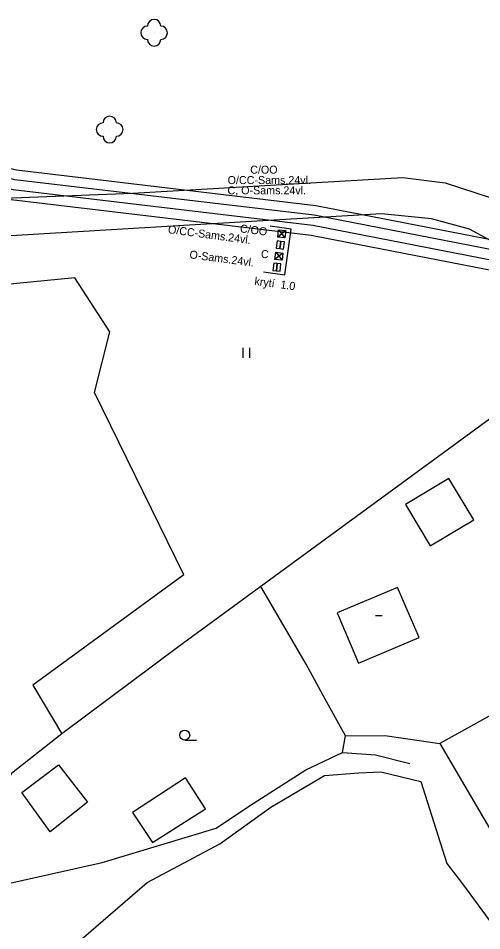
# Model space of a CAD drawing. Extents: x -836739 to -834468, y -1071001 to -1070126.
# Drawn here: x -836526 to -836491.3, y -1070268.6 to -1070200.2 of the extents above; entities that cross this region are included whole.
import ezdxf

# ---------------------------------------------------------------- set-up
doc = ezdxf.new("R2010")
doc.units = 0
for name, color, linetype in [('f001_pol_linie', 7, 'Continuous'), ('f001_pol_znacky', 7, 'Continuous'), ('f003_opt_sit_texty', 7, 'Continuous'), ('f006_osa_trasy', 7, 'Continuous'), ('f007_rezkynet_texty', 7, 'Continuous'), ('f007_rezkynet_znacky', 7, 'Continuous'), ('f309_trubka', 7, 'Continuous')]:
    doc.layers.add(name, color=color, linetype=linetype)

msp = doc.modelspace()

# ---------------------------------------------------------------- linework, layer by layer
at = {"layer": 'f001_pol_linie'}
for points in [[(-836565.55, -1070255.75), (-836568.29, -1070246.94), (-836565.3, -1070243.45), (-836558.59, -1070239.29), (-836553.32, -1070234.26), (-836550.36, -1070230.73), (-836544.63, -1070222.38), (-836541.42, -1070218.21), (-836539.02, -1070215.95), (-836535.5, -1070213.99), (-836517.48, -1070213.29), (-836497.22, -1070212.11), (-836494.05, -1070212.5), (-836489.39, -1070214.02), (-836485.93, -1070216.36), (-836482.28, -1070220.4), (-836478.23, -1070227.56), (-836471.79, -1070243.33), (-836465.92, -1070256.62), (-836463.85, -1070260.25), (-836463.13, -1070260.78)], [(-836466.54, -1070263.19), (-836474.56, -1070243.73), (-836478.12, -1070235.21), (-836483.33, -1070224.14), (-836486.58, -1070219.75), (-836489.27, -1070217.57), (-836492.22, -1070215.97), (-836495.08, -1070215.2), (-836498.82, -1070214.84), (-836513.64, -1070215.7), (-836532.05, -1070216.8), (-836534.5, -1070217.36), (-836537.57, -1070219.18), (-836540.24, -1070221.43), (-836545, -1070227.8), (-836549.52, -1070233.43), (-836552.32, -1070236.92), (-836557.98, -1070243.27), (-836562.8, -1070249.08), (-836563.01, -1070249.54), (-836561.48, -1070254.69), (-836565.55, -1070255.75)], [(-836513.64, -1070241.9), (-836520.33, -1070228.24), (-836519.17, -1070223.67), (-836521.79, -1070219.62), (-836540.24, -1070221.43)], [(-836481.49, -1070241.59), (-836481.74, -1070241), (-836484.22, -1070225.45), (-836507.86, -1070242.77), (-836514.01, -1070247.28)], [(-836493.77, -1070234.68), (-836497.03, -1070236.63), (-836495.17, -1070239.73), (-836491.91, -1070237.78), (-836493.77, -1070234.68)], [(-836513.64, -1070241.9), (-836524.94, -1070250.18), (-836522.78, -1070253.83)], [(-836501.52, -1070253.97), (-836503.04, -1070251.23), (-836504.47, -1070248.59), (-836507.86, -1070242.77)], [(-836497.61, -1070242.84), (-836502.15, -1070244.76)], [(-836496.01, -1070246.6), (-836497.61, -1070242.84)], [(-836502.15, -1070244.76), (-836500.55, -1070248.53)], [(-836500.55, -1070248.53), (-836496.01, -1070246.6)], [(-836514.01, -1070247.28), (-836522.78, -1070253.83)], [(-836484.13, -1070248.82), (-836494.44, -1070254.55), (-836490.71, -1070260.96)], [(-836522.78, -1070253.83), (-836526.55, -1070256.8), (-836527.02, -1070257.7), (-836529.71, -1070265.69)], [(-836508.71, -1070259.23), (-836504.49, -1070256.53), (-836501.74, -1070255.22), (-836501.52, -1070253.97), (-836498.58, -1070253.94), (-836494.44, -1070254.55)], [(-836501.74, -1070255.22), (-836499.27, -1070255.4), (-836496.7, -1070256.04)], [(-836525.78, -1070258.23), (-836523.02, -1070256.16), (-836520.84, -1070258.96)], [(-836521.88, -1070269.71), (-836516.37, -1070264.96), (-836510.93, -1070262.08), (-836507.11, -1070259.33), (-836503.08, -1070256.96), (-836500.52, -1070256.76), (-836498.86, -1070256.68), (-836495.87, -1070257.41), (-836493.93, -1070263.56), (-836492.75, -1070265.06), (-836486.76, -1070273.24)], [(-836517.49, -1070259.73), (-836515.98, -1070261.98), (-836512.01, -1070259.44), (-836513.5, -1070257.12), (-836517.49, -1070259.73)], [(-836523.65, -1070261.18), (-836525.78, -1070258.23)], [(-836529.71, -1070265.69), (-836519.75, -1070263.47), (-836511.22, -1070260.9), (-836508.71, -1070259.23)], [(-836520.84, -1070258.96), (-836523.65, -1070261.18)]]:
    msp.add_lwpolyline(points, dxfattribs=at)
at = {"layer": 'f001_pol_znacky'}
for p, q in [((-836509.18, -1070225.635), (-836509.18, -1070224.885)), ((-836508.68, -1070225.635), (-836508.68, -1070224.885)), ((-836499.27, -1070244.94), (-836498.77, -1070244.94)), ((-836513.57, -1070254.295), (-836512.695, -1070254.295))]:
    msp.add_line(p, q, dxfattribs=at)
for centre, radius in [((-836515.86, -1070201.25), 0.0005), ((-836519.19, -1070208.51), 0.0005), ((-836513.57, -1070253.92), 0.375)]:
    msp.add_circle(centre, radius, dxfattribs=at)
for centre, start, end in [((-836515.86, -1070200.75), 0, 179.99999), ((-836516.36, -1070201.25), 89.99999, 269.99999), ((-836515.36, -1070201.25), 270, 89.99999), ((-836515.86, -1070201.75), 179.99999, 359.99999), ((-836519.19, -1070208.01), 0, 179.99999), ((-836519.69, -1070208.51), 89.99999, 269.99999), ((-836518.69, -1070208.51), 270, 89.99999), ((-836519.19, -1070209.01), 179.99999, 359.99999)]:
    msp.add_arc(centre, 0.5, start, end, dxfattribs=at)
at = {"layer": 'f006_osa_trasy'}
msp.add_lwpolyline([(-836471.29, -1070247.06), (-836475.13, -1070240.07), (-836481.69, -1070223.19), (-836484.06, -1070219.25), (-836486.31, -1070218.35), (-836503.86, -1070214.94), (-836526.3, -1070212.27), (-836553.58, -1070205.67), (-836563.09, -1070200.8), (-836595.87, -1070176.09), (-836614.86, -1070165.34), (-836629.43, -1070164.09), (-836642.16, -1070162.86), (-836653.58, -1070160.22), (-836662.77, -1070161.03), (-836672.46, -1070165.03), (-836697.35, -1070176), (-836703.68, -1070184.13), (-836710.27, -1070188.76)], dxfattribs=at)
at = {"layer": 'f007_rezkynet_znacky'}
for p, q in [((-836505.586, -1070215.985), (-836507.17, -1070215.76)), ((-836505.999, -1070216.089), (-836506.601, -1070216.571)), ((-836506.541, -1070216.029), (-836506.059, -1070216.631)), ((-836506.071, -1070219.401), (-836505.586, -1070215.985)), ((-836506.209, -1070217.769), (-836506.811, -1070218.251)), ((-836506.751, -1070217.709), (-836506.269, -1070218.311)), ((-836507.656, -1070219.176), (-836506.071, -1070219.401))]:
    msp.add_line(p, q, dxfattribs=at)
for points in [[(-836505.999, -1070216.089), (-836506.059, -1070216.631), (-836506.601, -1070216.571), (-836506.541, -1070216.029)], [(-836506.369, -1070216.899), (-836506.64, -1070216.868), (-836506.702, -1070217.409), (-836506.431, -1070217.44)], [(-836506.098, -1070216.93), (-836506.369, -1070216.899), (-836506.431, -1070217.44), (-836506.16, -1070217.471)], [(-836506.209, -1070217.769), (-836506.269, -1070218.311), (-836506.811, -1070218.251), (-836506.751, -1070217.709)], [(-836506.629, -1070218.559), (-836506.9, -1070218.528), (-836506.962, -1070219.069), (-836506.691, -1070219.1)], [(-836506.358, -1070218.59), (-836506.629, -1070218.559), (-836506.691, -1070219.1), (-836506.42, -1070219.131)]]:
    msp.add_lwpolyline(points, close=True, dxfattribs=at)
at = {"layer": 'f309_trubka'}
for points in [[(-836710.701, -1070188.146), (-836710.087, -1070187.715), (-836704.203, -1070183.581), (-836697.826, -1070175.39), (-836672.754, -1070164.34), (-836662.95, -1070160.293), (-836653.527, -1070159.462), (-836642.039, -1070162.118), (-836629.362, -1070163.343), (-836614.633, -1070164.607), (-836595.458, -1070175.462), (-836562.69, -1070200.162), (-836553.317, -1070204.962), (-836526.167, -1070211.531), (-836503.744, -1070214.199), (-836486.097, -1070217.627), (-836483.547, -1070218.647), (-836481.014, -1070222.858), (-836474.449, -1070239.752), (-836470.632, -1070246.7)], [(-836471.29, -1070247.06), (-836475.13, -1070240.07), (-836481.69, -1070223.19), (-836484.06, -1070219.25), (-836486.31, -1070218.35), (-836503.86, -1070214.94), (-836526.3, -1070212.27), (-836553.58, -1070205.67), (-836563.09, -1070200.8), (-836595.87, -1070176.09), (-836614.86, -1070165.34), (-836629.43, -1070164.09), (-836642.16, -1070162.86), (-836653.58, -1070160.22), (-836662.77, -1070161.03), (-836672.46, -1070165.03), (-836697.35, -1070176), (-836703.68, -1070184.13), (-836709.656, -1070188.329), (-836710.27, -1070188.76)], [(-836709.839, -1070189.374), (-836709.225, -1070188.943), (-836703.157, -1070184.679), (-836696.874, -1070176.61), (-836672.166, -1070165.72), (-836662.59, -1070161.767), (-836653.633, -1070160.978), (-836642.281, -1070163.602), (-836629.498, -1070164.837), (-836615.087, -1070166.073), (-836596.282, -1070176.718), (-836563.49, -1070201.438), (-836553.843, -1070206.378), (-836526.433, -1070213.009), (-836503.976, -1070215.681), (-836486.523, -1070219.073), (-836484.573, -1070219.853), (-836482.366, -1070223.522), (-836475.811, -1070240.388), (-836471.948, -1070247.42)], [(-836709.408, -1070189.988), (-836708.794, -1070189.557), (-836702.634, -1070185.228), (-836696.398, -1070177.22), (-836671.872, -1070166.41), (-836662.41, -1070162.504), (-836653.686, -1070161.736), (-836642.402, -1070164.344), (-836629.566, -1070165.584), (-836615.314, -1070166.806), (-836596.694, -1070177.346), (-836563.89, -1070202.076), (-836554.106, -1070207.086), (-836526.566, -1070213.748), (-836504.092, -1070216.422), (-836486.736, -1070219.796), (-836485.086, -1070220.456), (-836483.042, -1070223.854), (-836476.492, -1070240.706), (-836472.606, -1070247.78)]]:
    msp.add_lwpolyline(points, dxfattribs=at)

# ---------------------------------------------------------------- texts
at = {"layer": 'f003_opt_sit_texty'}
for s, p in [('C/OO', (-836508.66, -1070211.82)), ('O/CC-Sams.24vl.', (-836510.35, -1070212.6)), ('C, O-Sams.24vl.', (-836510.36, -1070213.37))]:
    msp.add_text(s, height=0.6, dxfattribs=at).set_placement(p)
at = {"layer": 'f007_rezkynet_texty'}
for s, p in [('O/CC-Sams.24vl.', (-836514.849, -1070216.277)), ('C/OO', (-836509.459, -1070216.207)), ('O-Sams.24vl.', (-836513.239, -1070218.157)), ('C', (-836507.889, -1070218.107)), ('krytí  1.0', (-836508.369, -1070220.157))]:
    msp.add_text(s, height=0.6, rotation=352.45, dxfattribs=at).set_placement(p)

doc.saveas('drawing.dxf')
